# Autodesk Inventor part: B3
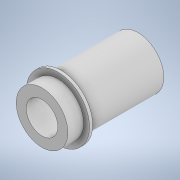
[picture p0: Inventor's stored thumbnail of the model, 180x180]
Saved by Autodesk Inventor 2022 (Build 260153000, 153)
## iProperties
Created: 2024-12
Part Number: B3
Material: 一般
Document SubType Name: Modeling
Designer: jsat7
Density: 1 g/cm^3
Appearance: 既定
Author: jsat7
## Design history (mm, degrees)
sketch "スケッチ1"
  geometry: C1 r 2.45 at (0, 0); 1 further point
  constraints: 1 centre point, 1 coincident
  dimensions: "d0" = 4.9 diameter of C1
extrude "押し出し1" new body sketch "スケッチ1" distance "d1" = 1.5; taper "d2" = 0 deg
sketch "スケッチ2"
  geometry: C1 r 3 at (0, 0); 1 further point
  constraints: 1 centre point, 1 coincident
  dimensions: "d3" = 6 diameter of C1
extrude "押し出し2" join sketch "スケッチ2" distance "d4" = 0.3; taper "d5" = 0 deg
sketch "スケッチ3"
  geometry: C1 r 2.45 at (0, 0); 1 further point
  constraints: 1 centre point, 1 coincident
  dimensions: "d6" = 4.9 diameter of C1
extrude "押し出し3" join sketch "スケッチ3" distance "d7" = 7.3; taper "d8" = 0 deg
sketch "スケッチ4"
  geometry: C1 r 1.5 at (0, 0); 1 further point
  constraints: 1 centre point, 1 coincident
  dimensions: "d9" = 3 diameter of C1
extrude "押し出し4" cut sketch "スケッチ4" distance "d10" = 10; taper "d11" = 0 deg
node "ソリッド1"
